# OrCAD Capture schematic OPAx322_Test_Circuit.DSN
size A; title: OPAx322x 20-MHz, 1.8-V, RRI/O, CMOS Operational Amplifier; rev: 1.4; note: Datasheet: SBOS538F  EVM: N/A
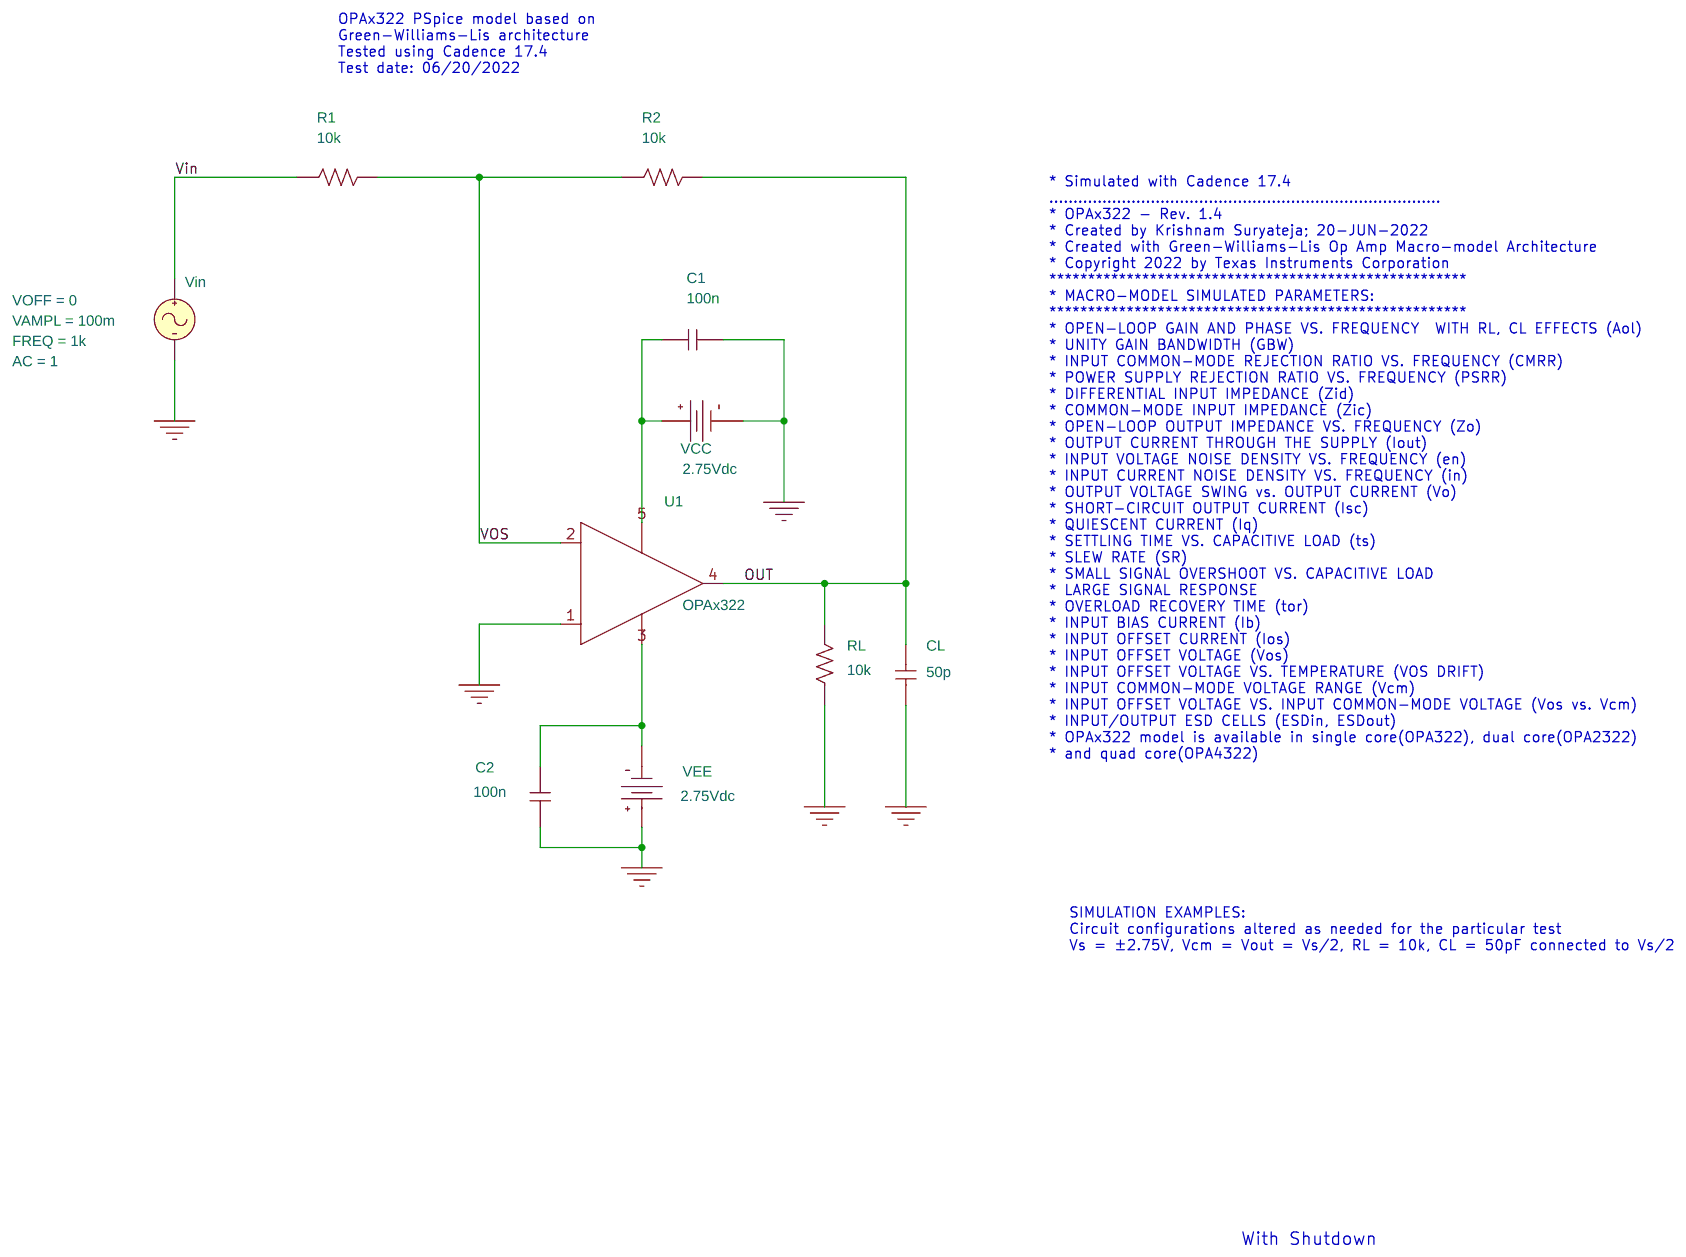
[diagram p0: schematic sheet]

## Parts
C1  100n  [cap196]
C2  100n  [cap196]
CL  50p  [cap196]
R1  10k  [AXRC05]
R2  10k  [AXRC05]
RL  10k  [AXRC05]
U1  OPAx322
VCC  VDC
VEE  VDC
Vin  VSIN

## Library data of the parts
C1 C2 CL = C
R1 R2 RL = R
U1 = OPAx322
VCC VEE = VDC: DC: 2.75Vdc
Vin = VSIN: AC: 1; FREQ: 1k; VAMPL: 100m; VOFF: 0

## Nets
Vin: R1.1 Vin.1(+)
0: C1.2 C2.1 CL.2 RL.1 U1.1(+) VCC.1(-) VEE.0(+) Vin.2(-)
OUT: CL.1 R2.2 RL.2 U1.4(OUT)
VOS: R1.2 R2.1 U1.2(-)
N27303: C1.1 U1.5(V+) VCC.0(+)
N27354: C2.2 U1.3(V-) VEE.1(-)

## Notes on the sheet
- OPAx322 PSpice model based on
  Green-Williams-Lis architecture
  Tested using Cadence 17.4
  Test date: 06/20/2022
- * Simulated with Cadence 17.4
  .................................................................................
  * OPAx322 - Rev. 1.4
  * Created by Krishnam Suryateja; 20-JUN-2022
  * Created with Green-Williams-Lis Op Amp Macro-model Architecture
  * Copyright 2022 by Texas Instruments Corporation
  ******************************************************
  * MACRO-MODEL SIMULATED PARAMETERS:
  ******************************************************
  * OPEN-LOOP GAIN AND PHASE VS. FREQUENCY  WITH RL, CL EFFECTS (Aol)
  * UNITY GAIN BANDWIDTH (GBW)
  * INPUT COMMON-MODE REJECTION RATIO VS. FREQUENCY (CMRR)
  * POWER SUPPLY REJECTION RATIO VS. FREQUENCY (PSRR)
  * DIFFERENTIAL INPUT IMPEDANCE (Zid)
  * COMMON-MODE INPUT IMPEDANCE (Zic)
  * OPEN-LOOP OUTPUT IMPEDANCE VS. FREQUENCY (Zo)
  * OUTPUT CURRENT THROUGH THE SUPPLY (Iout)
  * INPUT VOLTAGE NOISE DENSITY VS. FREQUENCY (en)
  * INPUT CURRENT NOISE DENSITY VS. FREQUENCY (in)
  * OUTPUT VOLTAGE SWING vs. OUTPUT CURRENT (Vo)
  * SHORT-CIRCUIT OUTPUT CURRENT (Isc)
  * QUIESCENT CURRENT (Iq)
  * SETTLING TIME VS. CAPACITIVE LOAD (ts)
  * SLEW RATE (SR)
  * SMALL SIGNAL OVERSHOOT VS. CAPACITIVE LOAD
  * LARGE SIGNAL RESPONSE
  * OVERLOAD RECOVERY TIME (tor)
  * INPUT BIAS CURRENT (Ib)
  * INPUT OFFSET CURRENT (Ios)
  * INPUT OFFSET VOLTAGE (Vos)
  * INPUT OFFSET VOLTAGE VS. TEMPERATURE (VOS DRIFT)
  * INPUT COMMON-MODE VOLTAGE RANGE (Vcm)
  * INPUT OFFSET VOLTAGE VS. INPUT COMMON-MODE VOLTAGE (Vos vs. Vcm)
  * INPUT/OUTPUT ESD CELLS (ESDin, ESDout)
  * OPAx322 model is available in single core(OPA322), dual core(OPA2322)
  * and quad core(OPA4322)
- SIMULATION EXAMPLES:
  Circuit configurations altered as needed for the particular test
  Vs = ±2.75V, Vcm = Vout = Vs/2, RL = 10k, CL = 50pF connected to Vs/2
- With Shutdown
